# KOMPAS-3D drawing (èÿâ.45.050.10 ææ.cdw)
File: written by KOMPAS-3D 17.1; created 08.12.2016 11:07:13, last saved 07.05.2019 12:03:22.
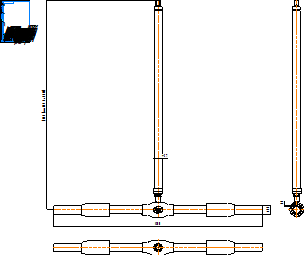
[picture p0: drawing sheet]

Sheet 1: A4, portrait

Title block, sheet 1: name: КШГ.45.050.10 СС; material: Внимание! Данный продукт является объектом авторского права ООО «Торговый Дом АДЛ». / Запрещается изменение, копирование, распространение / (в том числе путем копирования на другие сайты и ресурсы в Интернете) / или любое иное использование информации и объектов без предварительного / согласия правообладателя (ООО «Торговый Дом АДЛ»).; sheets: 1; organisation: ООО "Торговый дом АДЛ"; sheet format: A4; stored path: C:\Users\kka\KOMPAS_Work\Модели кранов для исследований\DN65\С удлинением\КШГ.35.050.25 СС ГЧ _ Шаровой кран БИВАЛ Ду50 Ру2,5 МПа полнопроходной под приварку, c удлинением штока H=950 Габаритный чертеж Lстр600.cdw; drawn by: Климкович К.А.; drawn by, date: 07.12.16

Views: Вид 1, Проекционный вид 2
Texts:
  Klimkovich
  ADL
  (от 287 до 5000)
Dimensions and other numbers on the sheet: 1500; 57; 63; 5,8; 1:1; 1; 07.12.16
